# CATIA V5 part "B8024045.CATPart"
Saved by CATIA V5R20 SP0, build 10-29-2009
Part number: B8024045
Revision: 6
Definition: design
Nomenclature: B8024045
Source: made
Description: NOT SPECIFIED
Bounding box of the stored display mesh (mm): x -33 to 33, y -33 to 33, z -12 to 45
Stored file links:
  C:\Users\Utente\Desktop\3D files B802\B8024045.CATPart
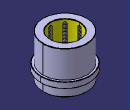
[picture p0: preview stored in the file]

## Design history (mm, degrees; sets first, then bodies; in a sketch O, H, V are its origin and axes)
Body1 "MANIFOLD_SOLID_BREP #38" (main body)
  Solid1: solid without history
Body2 "MANIFOLD_SOLID_BREP #76"
  Solid2: solid without history
Body3 "MANIFOLD_SOLID_BREP #114"
  Solid3: solid without history
Body4 "MANIFOLD_SOLID_BREP #152"
  Solid4: solid without history
Body5 "MANIFOLD_SOLID_BREP #190"
  Solid5: solid without history
Body6 "MANIFOLD_SOLID_BREP #228"
  Solid6: solid without history
Body7 "MANIFOLD_SOLID_BREP #266"
  Solid7: solid without history
Body8 "MANIFOLD_SOLID_BREP #304"
  Solid8: solid without history
Body9 "MANIFOLD_SOLID_BREP #2384"
  Solid9: solid without history
Body10 "MANIFOLD_SOLID_BREP #2422"
  Solid10: solid without history
Body11 "MANIFOLD_SOLID_BREP #2460"
  Solid11: solid without history
Body12 "MANIFOLD_SOLID_BREP #2498"
  Solid12: solid without history
Body13 "MANIFOLD_SOLID_BREP #2536"
  Solid13: solid without history
Body14 "MANIFOLD_SOLID_BREP #2574"
  Solid14: solid without history
Body15 "MANIFOLD_SOLID_BREP #2612"
  Solid15: solid without history
Body16 "MANIFOLD_SOLID_BREP #2650"
  Solid16: solid without history
Body17 "MANIFOLD_SOLID_BREP #2688"
  Solid17: solid without history
Body18 "MANIFOLD_SOLID_BREP #2726"
  Solid18: solid without history
Body19 "MANIFOLD_SOLID_BREP #2764"
  Solid19: solid without history
Body20 "MANIFOLD_SOLID_BREP #2802"
  Solid20: solid without history
Body21 "MANIFOLD_SOLID_BREP #2840"
  Solid21: solid without history
Body22 "MANIFOLD_SOLID_BREP #2878"
  Solid22: solid without history
Body23 "MANIFOLD_SOLID_BREP #2916"
  Solid23: solid without history
Body24 "MANIFOLD_SOLID_BREP #2954"
  Solid24: solid without history
Body25 "MANIFOLD_SOLID_BREP #2992"
  Solid25: solid without history
Body26 "MANIFOLD_SOLID_BREP #3030"
  Solid26: solid without history
Body27 "MANIFOLD_SOLID_BREP #3068"
  Solid27: solid without history
Body28 "MANIFOLD_SOLID_BREP #3106"
  Solid28: solid without history
Body29 "MANIFOLD_SOLID_BREP #3144"
  Solid29: solid without history
Body30 "MANIFOLD_SOLID_BREP #3182"
  Solid30: solid without history
Body31 "MANIFOLD_SOLID_BREP #3220"
  Solid31: solid without history
Body32 "MANIFOLD_SOLID_BREP #3258"
  Solid32: solid without history
Body33 "MANIFOLD_SOLID_BREP #3296"
  Solid33: solid without history
Body34 "MANIFOLD_SOLID_BREP #3334"
  Solid34: solid without history
Body35 "MANIFOLD_SOLID_BREP #3372"
  Solid35: solid without history
Body36 "MANIFOLD_SOLID_BREP #3410"
  Solid36: solid without history
Body37 "MANIFOLD_SOLID_BREP #3448"
  Solid37: solid without history
Body38 "MANIFOLD_SOLID_BREP #3486"
  Solid38: solid without history
Body39 "MANIFOLD_SOLID_BREP #3524"
  Solid39: solid without history
Body40 "MANIFOLD_SOLID_BREP #3562"
  Solid40: solid without history
Body41 "MANIFOLD_SOLID_BREP #3600"
  Solid41: solid without history
Body42 "MANIFOLD_SOLID_BREP #3638"
  Solid42: solid without history
Body43 "MANIFOLD_SOLID_BREP #3676"
  Solid43: solid without history
Body44 "MANIFOLD_SOLID_BREP #3714"
  Solid44: solid without history
Body45 "MANIFOLD_SOLID_BREP #3752"
  Solid45: solid without history
Body46 "MANIFOLD_SOLID_BREP #3790"
  Solid46: solid without history
Body47 "MANIFOLD_SOLID_BREP #3828"
  Solid47: solid without history
Body48 "MANIFOLD_SOLID_BREP #3866"
  Solid48: solid without history
Body49 "MANIFOLD_SOLID_BREP #3904"
  Solid49: solid without history
Body50 "MANIFOLD_SOLID_BREP #3942"
  Solid50: solid without history
Body51 "MANIFOLD_SOLID_BREP #3980"
  Solid51: solid without history
Body52 "MANIFOLD_SOLID_BREP #4018"
  Solid52: solid without history
Body53 "MANIFOLD_SOLID_BREP #4056"
  Solid53: solid without history
Body54 "MANIFOLD_SOLID_BREP #4094"
  Solid54: solid without history
Body55 "MANIFOLD_SOLID_BREP #4132"
  Solid55: solid without history
Body56 "MANIFOLD_SOLID_BREP #4170"
  Solid56: solid without history
Body57 "MANIFOLD_SOLID_BREP #4208"
  Solid57: solid without history
Body58 "MANIFOLD_SOLID_BREP #4246"
  Solid58: solid without history
Body59 "MANIFOLD_SOLID_BREP #4284"
  Solid59: solid without history
Body60 "MANIFOLD_SOLID_BREP #4322"
  Solid60: solid without history
Body61 "MANIFOLD_SOLID_BREP #4360"
  Solid61: solid without history
Body62 "MANIFOLD_SOLID_BREP #4398"
  Solid62: solid without history
Body63 "MANIFOLD_SOLID_BREP #4436"
  Solid63: solid without history
Body64 "MANIFOLD_SOLID_BREP #4474"
  Solid64: solid without history
Body65 "MANIFOLD_SOLID_BREP #4512"
  Solid65: solid without history
Body66 "MANIFOLD_SOLID_BREP #4550"
  Solid66: solid without history
Body67 "MANIFOLD_SOLID_BREP #4588"
  Solid67: solid without history
Body68 "MANIFOLD_SOLID_BREP #4626"
  Solid68: solid without history
Body69 "MANIFOLD_SOLID_BREP #4664"
  Solid69: solid without history
Body70 "MANIFOLD_SOLID_BREP #4702"
  Solid70: solid without history
Body71 "MANIFOLD_SOLID_BREP #4740"
  Solid71: solid without history
Body72 "MANIFOLD_SOLID_BREP #4778"
  Solid72: solid without history
Body73 "MANIFOLD_SOLID_BREP #4816"
  Solid73: solid without history
Body74 "MANIFOLD_SOLID_BREP #4854"
  Solid74: solid without history
Body75 "MANIFOLD_SOLID_BREP #4892"
  Solid75: solid without history
Body76 "MANIFOLD_SOLID_BREP #4930"
  Solid76: solid without history
Body77 "MANIFOLD_SOLID_BREP #4968"
  Solid77: solid without history
Body78 "MANIFOLD_SOLID_BREP #5006"
  Solid78: solid without history
Body79 "MANIFOLD_SOLID_BREP #5044"
  Solid79: solid without history
Body80 "MANIFOLD_SOLID_BREP #5082"
  Solid80: solid without history
Body81 "MANIFOLD_SOLID_BREP #5120"
  Solid81: solid without history
Body82 "MANIFOLD_SOLID_BREP #5158"
  Solid82: solid without history
Body83 "MANIFOLD_SOLID_BREP #5196"
  Solid83: solid without history
Body84 "MANIFOLD_SOLID_BREP #5234"
  Solid84: solid without history
Body85 "MANIFOLD_SOLID_BREP #5272"
  Solid85: solid without history
Body86 "MANIFOLD_SOLID_BREP #5310"
  Solid86: solid without history
Body87 "MANIFOLD_SOLID_BREP #5348"
  Solid87: solid without history
Body88 "MANIFOLD_SOLID_BREP #5386"
  Solid88: solid without history
Body89 "MANIFOLD_SOLID_BREP #5424"
  Solid89: solid without history
Body90 "MANIFOLD_SOLID_BREP #5462"
  Solid90: solid without history
Body91 "MANIFOLD_SOLID_BREP #5500"
  Solid91: solid without history
Body92 "MANIFOLD_SOLID_BREP #5538"
  Solid92: solid without history
Body93 "MANIFOLD_SOLID_BREP #5576"
  Solid93: solid without history
Body94 "MANIFOLD_SOLID_BREP #5614"
  Solid94: solid without history
Body95 "MANIFOLD_SOLID_BREP #5652"
  Solid95: solid without history
Body96 "MANIFOLD_SOLID_BREP #5690"
  Solid96: solid without history
Body97 "MANIFOLD_SOLID_BREP #5728"
  Solid97: solid without history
